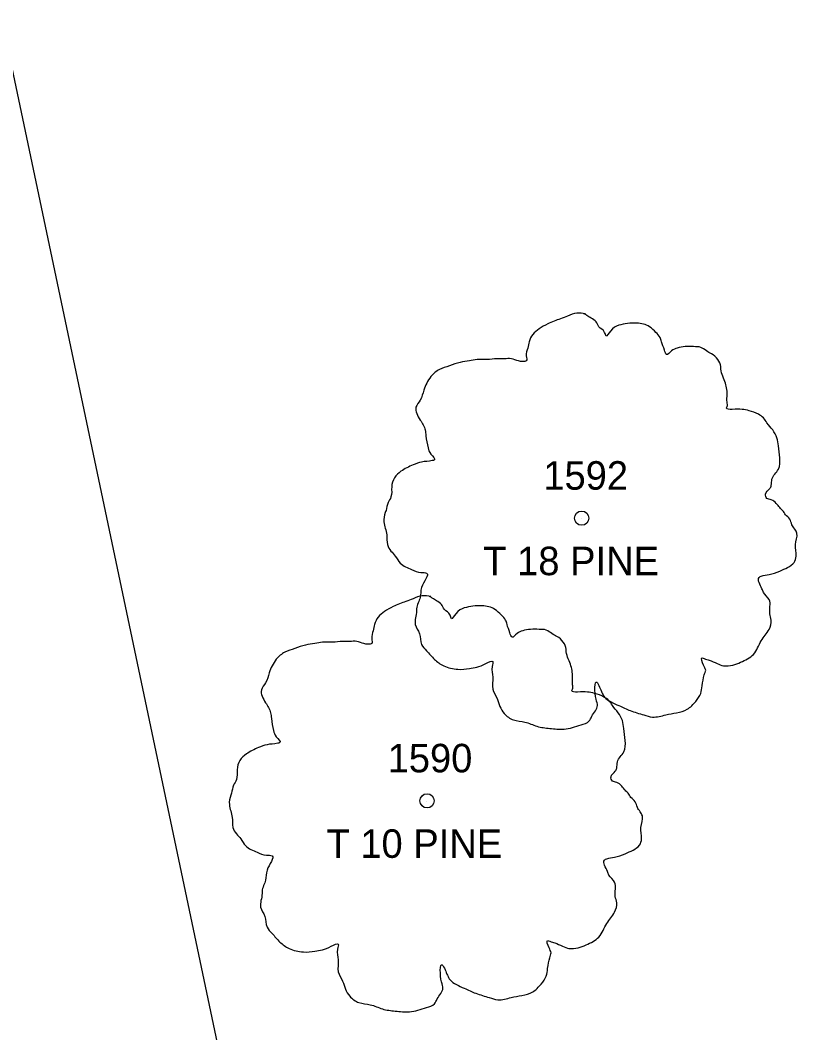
# Model space of a CAD drawing. Extents: x 1964982 to 1970452, y 1116335 to 1119906.
# Drawn here: x 1966670.35 to 1966697.63, y 1117458.33 to 1117493.86 of the extents above; entities that cross this region are included whole.
import ezdxf

# ---------------------------------------------------------------- set-up
doc = ezdxf.new("R2010")
doc.units = 0
for name, color, linetype in [('RD_EX_VEG', 7, 'Continuous'), ('RD_EX_VEG_txCode', 7, 'Continuous'), ('RD_HC_Data', 7, 'Continuous')]:
    doc.layers.add(name, color=color, linetype=linetype)

msp = doc.modelspace()

# ---------------------------------------------------------------- linework, layer by layer
at = {"layer": 'RD_EX_VEG'}
for centre, radius in [((1966690.05, 1117476.387), 0.25), ((1966690.05, 1117476.387), 0.25), ((1966690.038, 1117476.368), 0.0001), ((1966690.038, 1117476.368), 0.0001), ((1966684.627, 1117466.469), 0.25), ((1966684.627, 1117466.469), 0.25), ((1966684.614, 1117466.45), 0.0001), ((1966684.614, 1117466.45), 0.0001)]:
    msp.add_circle(centre, radius, dxfattribs=at)
for points in [[(1966690.182, 1117483.554), (1966689.882, 1117483.579), (1966689.558, 1117483.479), (1966689.308, 1117483.379), (1966689.083, 1117483.304), (1966688.858, 1117483.204), (1966688.558, 1117483.029), (1966688.333, 1117482.829), (1966688.208, 1117482.579), (1966688.158, 1117482.355), (1966688.108, 1117482.08), (1966688.108, 1117481.905), (1966687.983, 1117481.88), (1966687.833, 1117481.905), (1966687.583, 1117481.98), (1966687.333, 1117481.98), (1966687.084, 1117481.98), (1966686.734, 1117481.955), (1966686.384, 1117481.955), (1966686.109, 1117481.905), (1966685.784, 1117481.855), (1966685.409, 1117481.73), (1966685.059, 1117481.605), (1966684.76, 1117481.355), (1966684.51, 1117480.88), (1966684.385, 1117480.53), (1966684.235, 1117480.28), (1966684.385, 1117479.831), (1966684.56, 1117479.481), (1966684.585, 1117479.281), (1966684.66, 1117478.856), (1966684.76, 1117478.631), (1966684.885, 1117478.431), (1966684.81, 1117478.406), (1966684.435, 1117478.356), (1966684.135, 1117478.256), (1966683.71, 1117478.031), (1966683.485, 1117477.807), (1966683.385, 1117477.482), (1966683.36, 1117477.132), (1966683.26, 1117476.932), (1966683.185, 1117476.657), (1966683.16, 1117476.582), (1966683.11, 1117476.257), (1966683.21, 1117475.807), (1966683.235, 1117475.458), (1966683.36, 1117475.233), (1966683.51, 1117475.058), (1966683.685, 1117474.808), (1966684.085, 1117474.583), (1966684.41, 1117474.483), (1966684.61, 1117474.458), (1966684.435, 1117473.958), (1966684.385, 1117473.608), (1966684.26, 1117473.209), (1966684.26, 1117473.134), (1966684.21, 1117472.659), (1966684.36, 1117472.334), (1966684.435, 1117471.959), (1966684.61, 1117471.734), (1966684.885, 1117471.434), (1966685.209, 1117471.209), (1966685.709, 1117471.084), (1966686.109, 1117471.109), (1966686.684, 1117471.284), (1966686.934, 1117471.359), (1966686.909, 1117471.184), (1966686.934, 1117470.81), (1966686.934, 1117470.385), (1966687.084, 1117470.06), (1966687.184, 1117469.785), (1966687.333, 1117469.535), (1966687.658, 1117469.31), (1966688.058, 1117469.235), (1966688.483, 1117469.085), (1966688.933, 1117469.01), (1966689.433, 1117468.985), (1966690.032, 1117469.135), (1966690.307, 1117469.26), (1966690.407, 1117469.435), (1966690.607, 1117469.81), (1966690.557, 1117470.035), (1966690.582, 1117470.635), (1966690.682, 1117470.46), (1966690.857, 1117470.11), (1966691.357, 1117469.81), (1966691.757, 1117469.635), (1966692.231, 1117469.485), (1966692.531, 1117469.41), (1966693.006, 1117469.485), (1966693.381, 1117469.56), (1966693.756, 1117469.685), (1966694.056, 1117469.96), (1966694.23, 1117470.235), (1966694.28, 1117470.51), (1966694.355, 1117470.885), (1966694.405, 1117471.059)], [(1966690.182, 1117483.554), (1966689.882, 1117483.579), (1966689.558, 1117483.479), (1966689.308, 1117483.379), (1966689.083, 1117483.304), (1966688.858, 1117483.204), (1966688.558, 1117483.029), (1966688.333, 1117482.829), (1966688.208, 1117482.579), (1966688.158, 1117482.355), (1966688.108, 1117482.08), (1966688.108, 1117481.905), (1966687.983, 1117481.88), (1966687.833, 1117481.905), (1966687.583, 1117481.98), (1966687.333, 1117481.98), (1966687.084, 1117481.98), (1966686.734, 1117481.955), (1966686.384, 1117481.955), (1966686.109, 1117481.905), (1966685.784, 1117481.855), (1966685.409, 1117481.73), (1966685.059, 1117481.605), (1966684.76, 1117481.355), (1966684.51, 1117480.88), (1966684.385, 1117480.53), (1966684.235, 1117480.28), (1966684.385, 1117479.831), (1966684.56, 1117479.481), (1966684.585, 1117479.281), (1966684.66, 1117478.856), (1966684.76, 1117478.631), (1966684.885, 1117478.431), (1966684.81, 1117478.406), (1966684.435, 1117478.356), (1966684.135, 1117478.256), (1966683.71, 1117478.031), (1966683.485, 1117477.807), (1966683.385, 1117477.482), (1966683.36, 1117477.132), (1966683.26, 1117476.932), (1966683.185, 1117476.657), (1966683.16, 1117476.582), (1966683.11, 1117476.257), (1966683.21, 1117475.807), (1966683.235, 1117475.458), (1966683.36, 1117475.233), (1966683.51, 1117475.058), (1966683.685, 1117474.808), (1966684.085, 1117474.583), (1966684.41, 1117474.483), (1966684.61, 1117474.458), (1966684.435, 1117473.958), (1966684.385, 1117473.608), (1966684.26, 1117473.209), (1966684.26, 1117473.134), (1966684.21, 1117472.659), (1966684.36, 1117472.334), (1966684.435, 1117471.959), (1966684.61, 1117471.734), (1966684.885, 1117471.434), (1966685.209, 1117471.209), (1966685.709, 1117471.084), (1966686.109, 1117471.109), (1966686.684, 1117471.284), (1966686.934, 1117471.359), (1966686.909, 1117471.184), (1966686.934, 1117470.81), (1966686.934, 1117470.385), (1966687.084, 1117470.06), (1966687.184, 1117469.785), (1966687.333, 1117469.535), (1966687.658, 1117469.31), (1966688.058, 1117469.235), (1966688.483, 1117469.085), (1966688.933, 1117469.01), (1966689.433, 1117468.985), (1966690.032, 1117469.135), (1966690.307, 1117469.26), (1966690.407, 1117469.435), (1966690.607, 1117469.81), (1966690.557, 1117470.035), (1966690.582, 1117470.635), (1966690.682, 1117470.46), (1966690.857, 1117470.11), (1966691.357, 1117469.81), (1966691.757, 1117469.635), (1966692.231, 1117469.485), (1966692.531, 1117469.41), (1966693.006, 1117469.485), (1966693.381, 1117469.56), (1966693.756, 1117469.685), (1966694.056, 1117469.96), (1966694.23, 1117470.235), (1966694.28, 1117470.51), (1966694.355, 1117470.885), (1966694.405, 1117471.059)], [(1966694.405, 1117471.059), (1966694.33, 1117471.234), (1966694.28, 1117471.484), (1966694.355, 1117471.459), (1966694.53, 1117471.409), (1966694.805, 1117471.284), (1966695.03, 1117471.209), (1966695.355, 1117471.234), (1966695.63, 1117471.334), (1966696.08, 1117471.609), (1966696.355, 1117472.084), (1966696.629, 1117472.484), (1966696.704, 1117472.809), (1966696.654, 1117473.034), (1966696.629, 1117473.533), (1966696.429, 1117473.783), (1966696.379, 1117473.908), (1966696.28, 1117474.308), (1966696.355, 1117474.358), (1966696.629, 1117474.408), (1966697.004, 1117474.533), (1966697.279, 1117474.658), (1966697.504, 1117474.833), (1966697.579, 1117475.058), (1966697.554, 1117475.458), (1966697.604, 1117475.857), (1966697.529, 1117476.007), (1966697.429, 1117476.157), (1966697.354, 1117476.357), (1966697.204, 1117476.507), (1966697.104, 1117476.657), (1966697.004, 1117476.757), (1966696.879, 1117476.907), (1966696.704, 1117477.032), (1966696.554, 1117477.082), (1966696.504, 1117477.232), (1966696.654, 1117477.432), (1966696.704, 1117477.532), (1966696.729, 1117477.757), (1966696.954, 1117478.106), (1966697.004, 1117478.506), (1966696.954, 1117478.931), (1966696.904, 1117479.206), (1966696.754, 1117479.481), (1966696.554, 1117479.731), (1966696.429, 1117479.906), (1966696.255, 1117480.031), (1966695.93, 1117480.156), (1966695.68, 1117480.205), (1966695.33, 1117480.205), (1966695.13, 1117480.255), (1966695.155, 1117480.305), (1966695.155, 1117480.455), (1966695.155, 1117480.73), (1966695.08, 1117481.18), (1966694.93, 1117481.68), (1966694.93, 1117481.705), (1966694.83, 1117481.955), (1966694.605, 1117482.155), (1966694.43, 1117482.255), (1966694.23, 1117482.38), (1966693.981, 1117482.405), (1966693.681, 1117482.405), (1966693.406, 1117482.355), (1966693.206, 1117482.255), (1966693.031, 1117482.13), (1966692.956, 1117482.28), (1966692.856, 1117482.579), (1966692.806, 1117482.729), (1966692.656, 1117482.904), (1966692.431, 1117483.104), (1966691.981, 1117483.229), (1966691.357, 1117483.154), (1966691.057, 1117482.954), (1966690.907, 1117482.779), (1966690.857, 1117482.904), (1966690.657, 1117483.104), (1966690.557, 1117483.279), (1966690.382, 1117483.404), (1966690.232, 1117483.504), (1966690.132, 1117483.554)], [(1966694.405, 1117471.059), (1966694.33, 1117471.234), (1966694.28, 1117471.484), (1966694.355, 1117471.459), (1966694.53, 1117471.409), (1966694.805, 1117471.284), (1966695.03, 1117471.209), (1966695.355, 1117471.234), (1966695.63, 1117471.334), (1966696.08, 1117471.609), (1966696.355, 1117472.084), (1966696.629, 1117472.484), (1966696.704, 1117472.809), (1966696.654, 1117473.034), (1966696.629, 1117473.533), (1966696.429, 1117473.783), (1966696.379, 1117473.908), (1966696.28, 1117474.308), (1966696.355, 1117474.358), (1966696.629, 1117474.408), (1966697.004, 1117474.533), (1966697.279, 1117474.658), (1966697.504, 1117474.833), (1966697.579, 1117475.058), (1966697.554, 1117475.458), (1966697.604, 1117475.857), (1966697.529, 1117476.007), (1966697.429, 1117476.157), (1966697.354, 1117476.357), (1966697.204, 1117476.507), (1966697.104, 1117476.657), (1966697.004, 1117476.757), (1966696.879, 1117476.907), (1966696.704, 1117477.032), (1966696.554, 1117477.082), (1966696.504, 1117477.232), (1966696.654, 1117477.432), (1966696.704, 1117477.532), (1966696.729, 1117477.757), (1966696.954, 1117478.106), (1966697.004, 1117478.506), (1966696.954, 1117478.931), (1966696.904, 1117479.206), (1966696.754, 1117479.481), (1966696.554, 1117479.731), (1966696.429, 1117479.906), (1966696.255, 1117480.031), (1966695.93, 1117480.156), (1966695.68, 1117480.205), (1966695.33, 1117480.205), (1966695.13, 1117480.255), (1966695.155, 1117480.305), (1966695.155, 1117480.455), (1966695.155, 1117480.73), (1966695.08, 1117481.18), (1966694.93, 1117481.68), (1966694.93, 1117481.705), (1966694.83, 1117481.955), (1966694.605, 1117482.155), (1966694.43, 1117482.255), (1966694.23, 1117482.38), (1966693.981, 1117482.405), (1966693.681, 1117482.405), (1966693.406, 1117482.355), (1966693.206, 1117482.255), (1966693.031, 1117482.13), (1966692.956, 1117482.28), (1966692.856, 1117482.579), (1966692.806, 1117482.729), (1966692.656, 1117482.904), (1966692.431, 1117483.104), (1966691.981, 1117483.229), (1966691.357, 1117483.154), (1966691.057, 1117482.954), (1966690.907, 1117482.779), (1966690.857, 1117482.904), (1966690.657, 1117483.104), (1966690.557, 1117483.279), (1966690.382, 1117483.404), (1966690.232, 1117483.504), (1966690.132, 1117483.554)], [(1966684.758, 1117473.636), (1966684.459, 1117473.661), (1966684.134, 1117473.561), (1966683.884, 1117473.461), (1966683.659, 1117473.386), (1966683.434, 1117473.286), (1966683.134, 1117473.111), (1966682.909, 1117472.911), (1966682.784, 1117472.661), (1966682.734, 1117472.436), (1966682.684, 1117472.162), (1966682.684, 1117471.987), (1966682.559, 1117471.962), (1966682.409, 1117471.987), (1966682.16, 1117472.062), (1966681.91, 1117472.062), (1966681.66, 1117472.062), (1966681.31, 1117472.037), (1966680.96, 1117472.037), (1966680.685, 1117471.987), (1966680.36, 1117471.937), (1966679.986, 1117471.812), (1966679.636, 1117471.687), (1966679.336, 1117471.437), (1966679.086, 1117470.962), (1966678.961, 1117470.612), (1966678.811, 1117470.362), (1966678.961, 1117469.913), (1966679.136, 1117469.563), (1966679.161, 1117469.363), (1966679.236, 1117468.938), (1966679.336, 1117468.713), (1966679.461, 1117468.513), (1966679.386, 1117468.488), (1966679.011, 1117468.438), (1966678.711, 1117468.338), (1966678.286, 1117468.113), (1966678.061, 1117467.888), (1966677.961, 1117467.563), (1966677.936, 1117467.214), (1966677.837, 1117467.014), (1966677.762, 1117466.739), (1966677.737, 1117466.664), (1966677.687, 1117466.339), (1966677.787, 1117465.889), (1966677.812, 1117465.539), (1966677.936, 1117465.314), (1966678.086, 1117465.14), (1966678.261, 1117464.89), (1966678.661, 1117464.665), (1966678.986, 1117464.565), (1966679.186, 1117464.54), (1966679.011, 1117464.04), (1966678.961, 1117463.69), (1966678.836, 1117463.29), (1966678.836, 1117463.215), (1966678.786, 1117462.741), (1966678.936, 1117462.416), (1966679.011, 1117462.041), (1966679.186, 1117461.816), (1966679.461, 1117461.516), (1966679.786, 1117461.291), (1966680.285, 1117461.166), (1966680.685, 1117461.191), (1966681.26, 1117461.366), (1966681.51, 1117461.441), (1966681.485, 1117461.266), (1966681.51, 1117460.891), (1966681.51, 1117460.467), (1966681.66, 1117460.142), (1966681.76, 1117459.867), (1966681.91, 1117459.617), (1966682.235, 1117459.392), (1966682.634, 1117459.317), (1966683.059, 1117459.167), (1966683.509, 1117459.092), (1966684.009, 1117459.067), (1966684.609, 1117459.217), (1966684.883, 1117459.342), (1966684.983, 1117459.517), (1966685.183, 1117459.892), (1966685.133, 1117460.117), (1966685.158, 1117460.717), (1966685.258, 1117460.542), (1966685.433, 1117460.192), (1966685.933, 1117459.892), (1966686.333, 1117459.717), (1966686.808, 1117459.567), (1966687.107, 1117459.492), (1966687.582, 1117459.567), (1966687.957, 1117459.642), (1966688.332, 1117459.767), (1966688.632, 1117460.042), (1966688.807, 1117460.317), (1966688.857, 1117460.592), (1966688.932, 1117460.966), (1966688.982, 1117461.141)], [(1966684.758, 1117473.636), (1966684.459, 1117473.661), (1966684.134, 1117473.561), (1966683.884, 1117473.461), (1966683.659, 1117473.386), (1966683.434, 1117473.286), (1966683.134, 1117473.111), (1966682.909, 1117472.911), (1966682.784, 1117472.661), (1966682.734, 1117472.436), (1966682.684, 1117472.162), (1966682.684, 1117471.987), (1966682.559, 1117471.962), (1966682.409, 1117471.987), (1966682.16, 1117472.062), (1966681.91, 1117472.062), (1966681.66, 1117472.062), (1966681.31, 1117472.037), (1966680.96, 1117472.037), (1966680.685, 1117471.987), (1966680.36, 1117471.937), (1966679.986, 1117471.812), (1966679.636, 1117471.687), (1966679.336, 1117471.437), (1966679.086, 1117470.962), (1966678.961, 1117470.612), (1966678.811, 1117470.362), (1966678.961, 1117469.913), (1966679.136, 1117469.563), (1966679.161, 1117469.363), (1966679.236, 1117468.938), (1966679.336, 1117468.713), (1966679.461, 1117468.513), (1966679.386, 1117468.488), (1966679.011, 1117468.438), (1966678.711, 1117468.338), (1966678.286, 1117468.113), (1966678.061, 1117467.888), (1966677.961, 1117467.563), (1966677.936, 1117467.214), (1966677.837, 1117467.014), (1966677.762, 1117466.739), (1966677.737, 1117466.664), (1966677.687, 1117466.339), (1966677.787, 1117465.889), (1966677.812, 1117465.539), (1966677.936, 1117465.314), (1966678.086, 1117465.14), (1966678.261, 1117464.89), (1966678.661, 1117464.665), (1966678.986, 1117464.565), (1966679.186, 1117464.54), (1966679.011, 1117464.04), (1966678.961, 1117463.69), (1966678.836, 1117463.29), (1966678.836, 1117463.215), (1966678.786, 1117462.741), (1966678.936, 1117462.416), (1966679.011, 1117462.041), (1966679.186, 1117461.816), (1966679.461, 1117461.516), (1966679.786, 1117461.291), (1966680.285, 1117461.166), (1966680.685, 1117461.191), (1966681.26, 1117461.366), (1966681.51, 1117461.441), (1966681.485, 1117461.266), (1966681.51, 1117460.891), (1966681.51, 1117460.467), (1966681.66, 1117460.142), (1966681.76, 1117459.867), (1966681.91, 1117459.617), (1966682.235, 1117459.392), (1966682.634, 1117459.317), (1966683.059, 1117459.167), (1966683.509, 1117459.092), (1966684.009, 1117459.067), (1966684.609, 1117459.217), (1966684.883, 1117459.342), (1966684.983, 1117459.517), (1966685.183, 1117459.892), (1966685.133, 1117460.117), (1966685.158, 1117460.717), (1966685.258, 1117460.542), (1966685.433, 1117460.192), (1966685.933, 1117459.892), (1966686.333, 1117459.717), (1966686.808, 1117459.567), (1966687.107, 1117459.492), (1966687.582, 1117459.567), (1966687.957, 1117459.642), (1966688.332, 1117459.767), (1966688.632, 1117460.042), (1966688.807, 1117460.317), (1966688.857, 1117460.592), (1966688.932, 1117460.966), (1966688.982, 1117461.141)], [(1966688.982, 1117461.141), (1966688.907, 1117461.316), (1966688.857, 1117461.566), (1966688.932, 1117461.541), (1966689.107, 1117461.491), (1966689.381, 1117461.366), (1966689.606, 1117461.291), (1966689.931, 1117461.316), (1966690.206, 1117461.416), (1966690.656, 1117461.691), (1966690.931, 1117462.166), (1966691.206, 1117462.566), (1966691.281, 1117462.891), (1966691.231, 1117463.115), (1966691.206, 1117463.615), (1966691.006, 1117463.865), (1966690.956, 1117463.99), (1966690.856, 1117464.39), (1966690.931, 1117464.44), (1966691.206, 1117464.49), (1966691.58, 1117464.615), (1966691.855, 1117464.74), (1966692.08, 1117464.915), (1966692.155, 1117465.14), (1966692.13, 1117465.539), (1966692.18, 1117465.939), (1966692.105, 1117466.089), (1966692.005, 1117466.239), (1966691.93, 1117466.439), (1966691.78, 1117466.589), (1966691.68, 1117466.739), (1966691.58, 1117466.839), (1966691.456, 1117466.989), (1966691.281, 1117467.114), (1966691.131, 1117467.164), (1966691.081, 1117467.314), (1966691.231, 1117467.514), (1966691.281, 1117467.613), (1966691.306, 1117467.838), (1966691.531, 1117468.188), (1966691.58, 1117468.588), (1966691.531, 1117469.013), (1966691.481, 1117469.288), (1966691.331, 1117469.563), (1966691.131, 1117469.813), (1966691.006, 1117469.987), (1966690.831, 1117470.112), (1966690.506, 1117470.237), (1966690.256, 1117470.287), (1966689.906, 1117470.287), (1966689.706, 1117470.337), (1966689.731, 1117470.387), (1966689.731, 1117470.537), (1966689.731, 1117470.812), (1966689.656, 1117471.262), (1966689.506, 1117471.762), (1966689.506, 1117471.787), (1966689.406, 1117472.037), (1966689.182, 1117472.236), (1966689.007, 1117472.336), (1966688.807, 1117472.461), (1966688.557, 1117472.486), (1966688.257, 1117472.486), (1966687.982, 1117472.436), (1966687.782, 1117472.336), (1966687.607, 1117472.211), (1966687.532, 1117472.361), (1966687.432, 1117472.661), (1966687.382, 1117472.811), (1966687.232, 1117472.986), (1966687.008, 1117473.186), (1966686.558, 1117473.311), (1966685.933, 1117473.236), (1966685.633, 1117473.036), (1966685.483, 1117472.861), (1966685.433, 1117472.986), (1966685.233, 1117473.186), (1966685.133, 1117473.361), (1966684.958, 1117473.486), (1966684.808, 1117473.586), (1966684.708, 1117473.636)], [(1966688.982, 1117461.141), (1966688.907, 1117461.316), (1966688.857, 1117461.566), (1966688.932, 1117461.541), (1966689.107, 1117461.491), (1966689.381, 1117461.366), (1966689.606, 1117461.291), (1966689.931, 1117461.316), (1966690.206, 1117461.416), (1966690.656, 1117461.691), (1966690.931, 1117462.166), (1966691.206, 1117462.566), (1966691.281, 1117462.891), (1966691.231, 1117463.115), (1966691.206, 1117463.615), (1966691.006, 1117463.865), (1966690.956, 1117463.99), (1966690.856, 1117464.39), (1966690.931, 1117464.44), (1966691.206, 1117464.49), (1966691.58, 1117464.615), (1966691.855, 1117464.74), (1966692.08, 1117464.915), (1966692.155, 1117465.14), (1966692.13, 1117465.539), (1966692.18, 1117465.939), (1966692.105, 1117466.089), (1966692.005, 1117466.239), (1966691.93, 1117466.439), (1966691.78, 1117466.589), (1966691.68, 1117466.739), (1966691.58, 1117466.839), (1966691.456, 1117466.989), (1966691.281, 1117467.114), (1966691.131, 1117467.164), (1966691.081, 1117467.314), (1966691.231, 1117467.514), (1966691.281, 1117467.613), (1966691.306, 1117467.838), (1966691.531, 1117468.188), (1966691.58, 1117468.588), (1966691.531, 1117469.013), (1966691.481, 1117469.288), (1966691.331, 1117469.563), (1966691.131, 1117469.813), (1966691.006, 1117469.987), (1966690.831, 1117470.112), (1966690.506, 1117470.237), (1966690.256, 1117470.287), (1966689.906, 1117470.287), (1966689.706, 1117470.337), (1966689.731, 1117470.387), (1966689.731, 1117470.537), (1966689.731, 1117470.812), (1966689.656, 1117471.262), (1966689.506, 1117471.762), (1966689.506, 1117471.787), (1966689.406, 1117472.037), (1966689.182, 1117472.236), (1966689.007, 1117472.336), (1966688.807, 1117472.461), (1966688.557, 1117472.486), (1966688.257, 1117472.486), (1966687.982, 1117472.436), (1966687.782, 1117472.336), (1966687.607, 1117472.211), (1966687.532, 1117472.361), (1966687.432, 1117472.661), (1966687.382, 1117472.811), (1966687.232, 1117472.986), (1966687.008, 1117473.186), (1966686.558, 1117473.311), (1966685.933, 1117473.236), (1966685.633, 1117473.036), (1966685.483, 1117472.861), (1966685.433, 1117472.986), (1966685.233, 1117473.186), (1966685.133, 1117473.361), (1966684.958, 1117473.486), (1966684.808, 1117473.586), (1966684.708, 1117473.636)]]:
    msp.add_spline(points, degree=3, dxfattribs=at)
at = {"layer": 'RD_HC_Data'}
msp.add_line((1966684.871, 1117421.945), (1966664.447, 1117518.825), dxfattribs=at)

# ---------------------------------------------------------------- texts
at = {"layer": 'RD_EX_VEG_txCode'}
for s, p in [('1592', (1966688.704, 1117477.387)), ('1592', (1966688.704, 1117477.387)), ('T 18 PINE', (1966686.598, 1117474.387)), ('T 18 PINE', (1966686.598, 1117474.387)), ('1590', (1966683.241, 1117467.469)), ('1590', (1966683.241, 1117467.469)), ('T 10 PINE', (1966681.095, 1117464.469)), ('T 10 PINE', (1966681.095, 1117464.469))]:
    msp.add_text(s, height=1, dxfattribs=at).set_placement(p)

doc.saveas('drawing.dxf')
